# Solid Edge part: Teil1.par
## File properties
Author: administrator
Template: Normal.par
Last saved by: Administrator
Revision: 4
Application: Solid Edge
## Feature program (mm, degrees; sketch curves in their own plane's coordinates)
sketch for "unnamed Protrusion 1" plane through (0, 0, 0) normal (0, -1, 0) x-axis (1, 0, 0)
  line (-40.7867, -23.8133) -> (-40.7867, 16.1867)
  line (-40.7867, 16.1867) -> (-10.7867, 16.1867)
  line (-10.7867, 16.1867) -> (-10.7867, -3.8133)
  line (-10.7867, -3.8133) -> (9.2133, -3.8133)
  line (9.2133, -3.8133) -> (9.2133, -23.8133)
  line (9.2133, -23.8133) -> (-40.7867, -23.8133)
extrude "unnamed Protrusion 1" add finite 40 along -normal
sketch for "unnamed Cutout 1" plane through (-25.7867, 20, 16.1867) normal (0, 0, 1) x-axis (1, 0, 0)
  circle centre (0, 0) radius 5
extrude "unnamed Cutout 1" cut finite 66.675 along -normal
